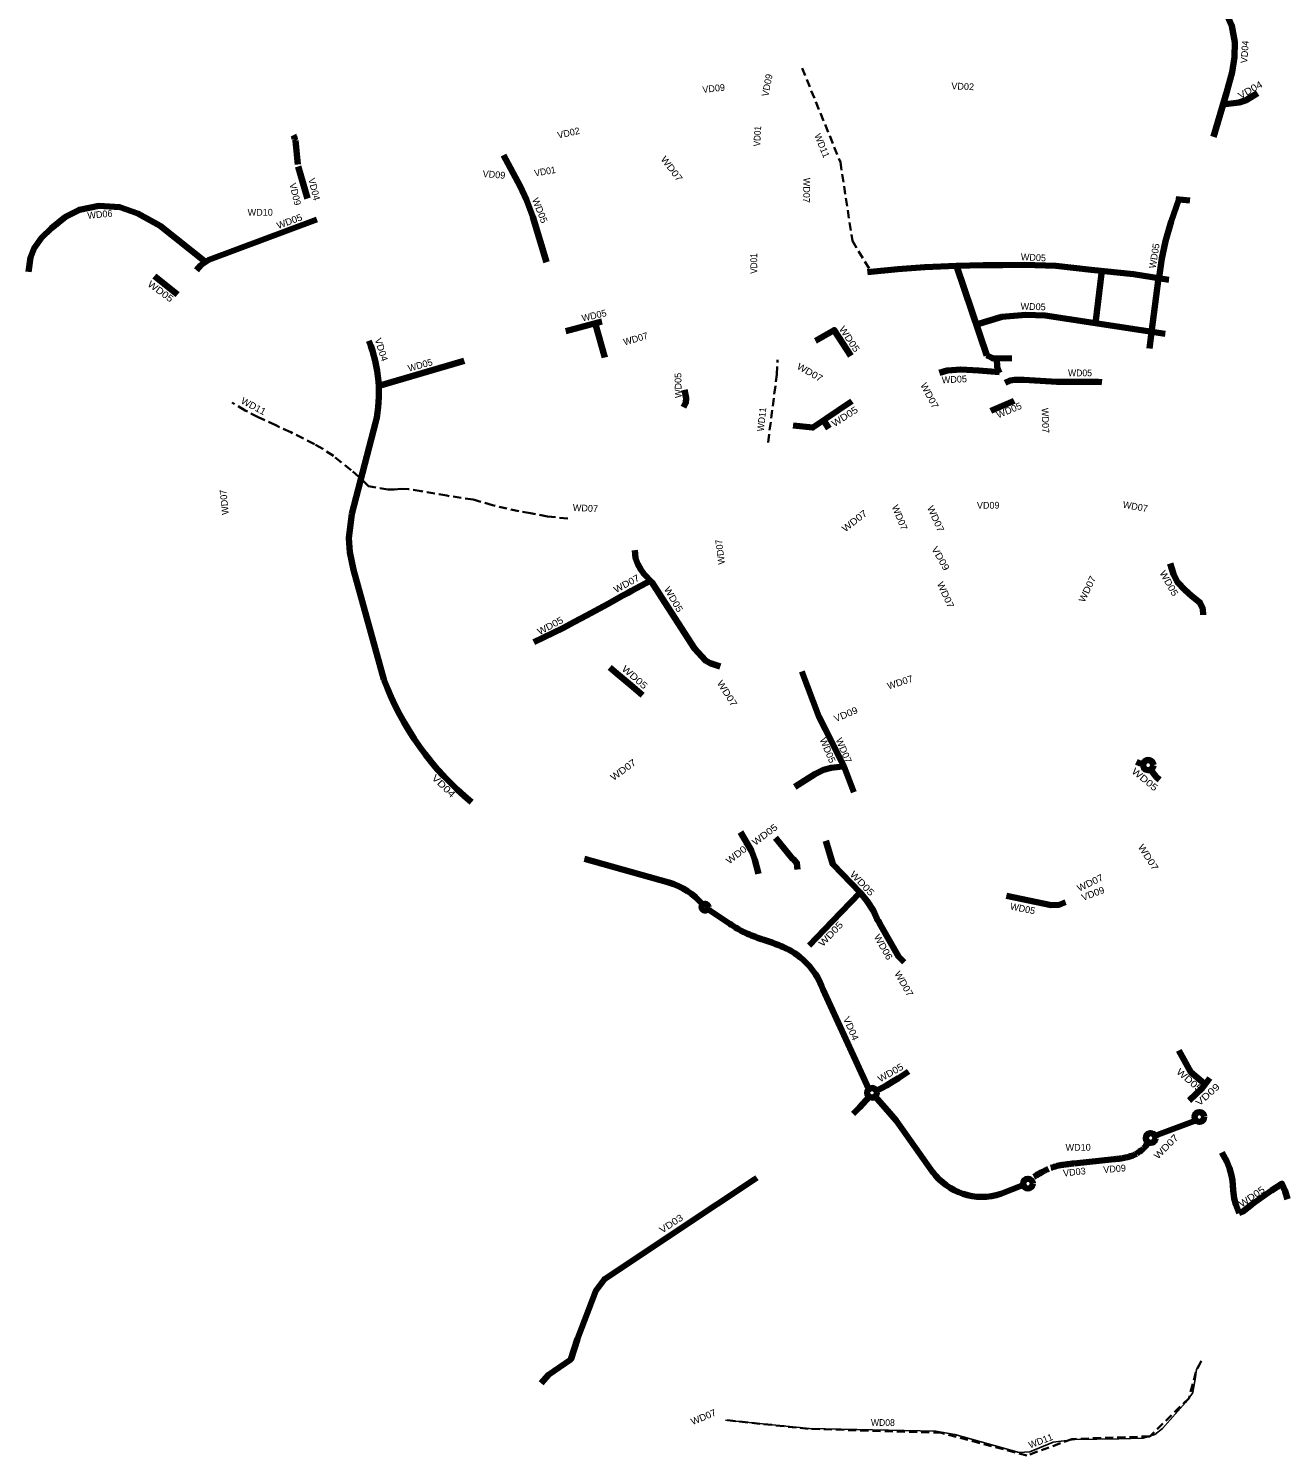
# Model space of a CAD drawing. Extents: x -650082 to -644047, y -1073134 to -1066669.
# Drawn here: x -650082 to -646363, y -1073058 to -1068842 of the extents above; entities that cross this region are included whole.
import ezdxf

# ---------------------------------------------------------------- set-up
doc = ezdxf.new("R2010")
doc.units = 0
doc.header["$LTSCALE"] = 8
doc.linetypes.add('MEDIUM_DASHED', pattern=[4.5, 3, -1.5])
for name, color, linetype in [('1', 7, 'Continuous'), ('10', 7, 'Continuous'), ('14', 7, 'Continuous'), ('2', 7, 'Continuous'), ('3', 7, 'Continuous'), ('4', 7, 'Continuous'), ('5', 7, 'Continuous'), ('6', 7, 'Continuous'), ('7', 7, 'Continuous'), ('9', 7, 'Continuous')]:
    doc.layers.add(name, color=color, linetype=linetype)
for name, color, linetype, lineweight in [('11', 7, 'Continuous', 106), ('12', 7, 'Continuous', 106), ('13', 7, 'MEDIUM_DASHED', 35), ('47', 7, 'Continuous', 106), ('51', 7, 'Continuous', 106), ('8', 7, 'Continuous', 25)]:
    doc.layers.add(name, color=color, linetype=linetype, lineweight=lineweight)

msp = doc.modelspace()

# ---------------------------------------------------------------- linework, layer by layer
at = {"layer": '11'}
for p, q in [((-649286.296, -1069243.402), (-649294.037, -1069172.192)), ((-649258.547, -1069344.39), (-649285.681, -1069249.06)), ((-649126.823, -1070275.677), (-649056.809, -1070006.786)), ((-648190.636, -1071365.392), (-648439.544, -1071295.299)), ((-647735.858, -1071680.067), (-647599.793, -1071975.634))]:
    msp.add_line(p, q, dxfattribs=at)
for points in [[(-646581.274, -1069162.086), (-646543.734, -1069031.454), (-646526.307, -1068970.81), (-646520.034, -1068926.895), (-646519.124, -1068882.525), (-646527.13, -1068833.717), (-646541.089, -1068803.463), (-646555.823, -1068777.863), (-646576.76, -1068753.039), (-646603.929, -1068734.295), (-646632.204, -1068718.474)], [(-646553.797, -1069066.473), (-646505.955, -1069060.333), (-646484.805, -1069053.474), (-646451.286, -1069033.122)], [(-649126.823, -1070275.677), (-649136.116, -1070347.82), (-649133.06, -1070389.586), (-649121.855, -1070441.538), (-649032.534, -1070765.134)], [(-648075.374, -1071443.872), (-648022.004, -1071479.581), (-648016.461, -1071483.285), (-648010.907, -1071486.974), (-648005.332, -1071490.629), (-647999.724, -1071494.234), (-647994.074, -1071497.773), (-647988.372, -1071501.227), (-647982.61, -1071504.58), (-647976.78, -1071507.812), (-647970.874, -1071510.906), (-647963.887, -1071513.957), (-647958.108, -1071516.621), (-647952.275, -1071519.164), (-647946.395, -1071521.599), (-647940.477, -1071523.938), (-647934.527, -1071526.195), (-647928.551, -1071528.382), (-647922.556, -1071530.515), (-647916.545, -1071532.605), (-647910.525, -1071534.668), (-647904.5, -1071536.717), (-647895.595, -1071539.745), (-647889.576, -1071541.81), (-647883.568, -1071543.908), (-647877.578, -1071546.054), (-647871.61, -1071548.265), (-647865.673, -1071550.555), (-647859.774, -1071552.942), (-647853.921, -1071555.438), (-647848.123, -1071558.061), (-647842.39, -1071560.823), (-647836.733, -1071563.738)]]:
    msp.add_lwpolyline(points, dxfattribs=at)
msp.add_circle((-648083.781, -1071438.172), 10.157, dxfattribs=at)
for centre, radius, start, end in [((-649390.897, -1069197.054), 100, 14.39558, 23.46117), ((-649452.625, -1069917.995), 405.652, 347.35635, 22.18649), ((-648232.695, -1070467.567), 853.398, 200.40686, 230.69896), ((-648244.965, -1071557.871), 200, 39.49461, 74.23772), ((-647937.958, -1071753.418), 215, 19.9479, 61.91292)]:
    msp.add_arc(centre, radius, start, end, dxfattribs=at)
at = {"layer": '12'}
for p, q in [((-646754.674, -1072114.023), (-646633.694, -1072068.165)), ((-646993.404, -1072195.535), (-646875.615, -1072182.532)), ((-647145.028, -1072259.442), (-647209.69, -1072285.315))]:
    msp.add_line(p, q, dxfattribs=at)
for points in [[(-647646.641, -1072049.031), (-647627.876, -1072030.328), (-647598.733, -1071998.754)], [(-647581.398, -1071997.866), (-647544.374, -1072039.387), (-647519.615, -1072068.332), (-647409.551, -1072222.875)], [(-646876.248, -1072183.165), (-646872.383, -1072182.737), (-646868.519, -1072182.3), (-646864.657, -1072181.844), (-646860.798, -1072181.36), (-646856.944, -1072180.839), (-646853.097, -1072180.272), (-646849.258, -1072179.649), (-646845.43, -1072178.963), (-646841.617, -1072178.202), (-646837.82, -1072177.36), (-646834.045, -1072176.427), (-646830.296, -1072175.394), (-646826.578, -1072174.254), (-646822.898, -1072172.998), (-646819.262, -1072171.619), (-646815.677, -1072170.111), (-646812.154, -1072168.466), (-646808.701, -1072166.678)], [(-647112.659, -1072235.417), (-647108.405, -1072232.79), (-647104.143, -1072230.176), (-647099.863, -1072227.591), (-647095.557, -1072225.05), (-647091.218, -1072222.565), (-647086.838, -1072220.154), (-647082.411, -1072217.83), (-647077.93, -1072215.611), (-647073.393, -1072213.512), (-647068.794, -1072211.549)], [(-647062.642, -1072208.565), (-647057.907, -1072206.959), (-647053.125, -1072205.5), (-647048.303, -1072204.179), (-647043.448, -1072202.984), (-647038.565, -1072201.905), (-647033.661, -1072200.931), (-647028.739, -1072200.051), (-647023.804, -1072199.253), (-647018.857, -1072198.525), (-647013.902, -1072197.856), (-647008.941, -1072197.235), (-647003.975, -1072196.649), (-646999.007, -1072196.086), (-646994.037, -1072195.536)], [(-647930.391, -1072238.053), (-647936.91, -1072242.12), (-648048.17, -1072316.094), (-648380.845, -1072537.281), (-648405.937, -1072571.667), (-648460.352, -1072713.39), (-648480.403, -1072774.677), (-648546.627, -1072820.111), (-648567.38, -1072844.77)]]:
    msp.add_lwpolyline(points, dxfattribs=at)
for centre in [(-647590.655, -1071986.8), (-646623.358, -1072058.099), (-646767.624, -1072120.384), (-647130.12, -1072255.012)]:
    msp.add_circle(centre, 14.428, dxfattribs=at)
for centre, radius, start, end in [((-646851.756, -1072087.012), 90, 298.5808, 324.78461), ((-647266.212, -1072116.452), 178.071, 215.23547, 288.50636)]:
    msp.add_arc(centre, radius, start, end, dxfattribs=at)
at = {"layer": '13'}
for points in [[(-647796.971, -1068958.769), (-647683.968, -1069236.597), (-647648.396, -1069468.745), (-647594.062, -1069560.317), (-647340.265, -1069541.717), (-647253.655, -1069810.08), (-647231.91, -1069823.971)], [(-647897.53, -1070064.61), (-647871.671, -1069864.156), (-647869.45, -1069820.63)], [(-648489.42, -1070289.79), (-648549.11, -1070283.64), (-648599.41, -1070274.03), (-648633.75, -1070268.38), (-648711.24, -1070250.44), (-648768.32, -1070233.86), (-648846.76, -1070222.17), (-648921.87, -1070208.67), (-648959.67, -1070203.09), (-648981.35, -1070202.4), (-649002.23, -1070203.94), (-649021.05, -1070203.56), (-649078.099, -1070194.501), (-649106.06, -1070166.8), (-649129.57, -1070146.73), (-649181.7, -1070104.45), (-649213.21, -1070083.53), (-649237.78, -1070069.79), (-649307.84, -1070034.18), (-649351.66, -1070014.26), (-649403.65, -1069989.85), (-649442.47, -1069970.36), (-649481, -1069947.32)], [(-646618.098, -1072779.957), (-646633.878, -1072812.319), (-646654.064, -1072888.773), (-646770.097, -1073001.842), (-647000.119, -1073009.906), (-647132.968, -1073058.363), (-647385.213, -1072991.734), (-647778.715, -1072979.619), (-648025.915, -1072953.371)]]:
    msp.add_lwpolyline(points, dxfattribs=at)
at = {"layer": '47'}
for p, q in [((-646692.985, -1069346.026), (-646651.217, -1069350.274)), ((-647339.967, -1069545.744), (-647251.088, -1069808.426)), ((-646912.03, -1069558.076), (-646930.389, -1069712.594)), ((-649642.332, -1069628.173), (-649710.271, -1069574.044)), ((-647207.164, -1069694.062), (-647282.295, -1069716.194)), ((-648494.915, -1069736.521), (-648388.804, -1069707.486)), ((-648379.302, -1069814.125), (-648408.537, -1069712.885)), ((-649043.757, -1069896.46), (-648795.401, -1069824.199)), ((-647170.402, -1069942.221), (-647239.362, -1069971.673)), ((-647718.115, -1070024.038), (-647733.777, -1069999.441)), ((-647672.743, -1071023.641), (-647643.873, -1071098.745)), ((-646808.839, -1071008.864), (-646795.926, -1071014.301)), ((-647824.318, -1071296.38), (-647875.239, -1071233.632)), ((-647708.122, -1071480.45), (-647626.882, -1071395.872)), ((-647708.122, -1071480.45), (-647775.697, -1071551.243))]:
    msp.add_line(p, q, dxfattribs=at)
for points in [[(-648552.408, -1069532.362), (-648592.697, -1069398.642), (-648611.424, -1069347.704), (-648629.402, -1069308.002), (-648679.548, -1069216.178)], [(-646742.322, -1069576.725), (-646734.087, -1069520.908), (-646723.107, -1069469.667), (-646706.636, -1069412.02), (-646684.285, -1069346.911)], [(-649586.177, -1069556.212), (-649573.053, -1069541.298), (-649550.047, -1069525.713), (-649230.786, -1069405.644)], [(-647603.51, -1069561.425), (-647514.414, -1069553.281), (-647434.342, -1069547.122), (-647341.331, -1069542.596), (-647262.07, -1069540.647), (-647204.248, -1069540.647), (-647140.134, -1069540.07), (-647047.049, -1069543.256), (-646943.2, -1069554.795), (-646817.923, -1069567.982), (-646714.075, -1069584.466)], [(-646744.044, -1069579.015), (-646764.641, -1069739.238), (-646770.927, -1069787.596)], [(-646724.352, -1069743.581), (-647078.839, -1069690.268), (-647135.789, -1069688.123), (-647207.164, -1069694.062)], [(-647757.476, -1069764.575), (-647701.982, -1069733.103), (-647653.087, -1069809.089)], [(-647251.088, -1069808.426), (-647232.613, -1069816.264), (-647177.241, -1069817.194)], [(-647213.795, -1069859.205), (-647220.933, -1069841.605), (-647221.408, -1069819.284)], [(-647390.821, -1069859.073), (-647368.021, -1069852.558), (-647328.004, -1069849.767), (-647274.492, -1069852.093), (-647213.899, -1069857.686)], [(-647197.567, -1069888.373), (-647182.853, -1069882.067), (-647168.927, -1069879.439), (-647141.6, -1069879.965), (-647044.065, -1069885.918), (-646922.882, -1069885.918), (-646911.17, -1069886.938)], [(-648147.091, -1069960.576), (-648140.266, -1069946.926), (-648139.508, -1069934.035), (-648144.058, -1069909.01)], [(-647650.097, -1069942.883), (-647765.549, -1070020.915), (-647823.598, -1070014.961)], [(-648290.966, -1070383.374), (-648288.845, -1070406.899), (-648282.079, -1070425.044), (-648273.16, -1070440.728), (-648264.17, -1070453.236), (-648241.202, -1070478.118), (-648211.195, -1070523.918)], [(-646709.343, -1070422.319), (-646700.372, -1070454.216), (-646687.863, -1070477.44), (-646666.258, -1070500.316), (-646645.289, -1070519.379), (-646621.777, -1070537.807), (-646613.517, -1070556.235), (-646612.246, -1070574.663)], [(-648589.664, -1070655.082), (-648504.268, -1070613.585), (-648469.046, -1070594.986), (-648434.122, -1070576.22), (-648370.201, -1070541.371), (-648326.641, -1070517.498), (-648313.175, -1070510.435), (-648300.652, -1070503.633), (-648244.358, -1070473.301)], [(-648039.532, -1070726.638), (-648068.169, -1070717.378), (-648082.709, -1070709.44), (-648115.092, -1070674.163), (-648211.195, -1070523.918)], [(-648268.369, -1070811.262), (-648303.087, -1070781.942), (-648344.753, -1070748.129), (-648364.772, -1070729.983)], [(-647798.303, -1070741.695), (-647747.4, -1070874.36), (-647727.829, -1070913.158), (-647672.743, -1071023.641)], [(-647677.55, -1071022.921), (-647710.774, -1071025.971), (-647733.735, -1071032.504), (-647759.543, -1071045.17), (-647818.707, -1071082.607)], [(-646741.751, -1071062.202), (-646751.573, -1071052.898), (-646766.082, -1071034.526)], [(-647925.368, -1071339.891), (-647936.852, -1071298.253), (-647946.561, -1071272.093), (-647978.731, -1071216.254)], [(-647727.338, -1071242.207), (-647706.62, -1071310.667), (-647625.213, -1071395.211), (-647604.958, -1071420.095), (-647586.504, -1071448.747), (-647573.087, -1071478.317)], [(-647810.393, -1071327.127), (-647812.572, -1071307.894), (-647823.337, -1071295.659)], [(-647193.49, -1071404.445), (-647061.509, -1071431.827), (-647037.352, -1071430.861), (-647019.146, -1071423.327)], [(-646684.409, -1071862), (-646648.676, -1071926.01), (-646609.296, -1071959.529)], [(-647577.687, -1071980.477), (-647548.027, -1071965.02), (-647528.6, -1071953.175), (-647512.49, -1071943.224), (-647482.989, -1071923.852)], [(-646592.707, -1071943.76), (-646614.335, -1071972.381), (-646653.429, -1072008.981)], [(-646556.924, -1072163.008), (-646541.975, -1072190.142), (-646534.08, -1072209.348), (-646528.451, -1072231.169), (-646526.022, -1072245.895), (-646524.078, -1072274.419), (-646520.515, -1072298.567), (-646515.575, -1072317.043), (-646505.446, -1072341.949)], [(-646505.446, -1072341.949), (-646496.463, -1072338.193), (-646468.402, -1072317.124), (-646451.071, -1072304.158), (-646409.932, -1072275.634), (-646379.686, -1072255.456), (-646370.251, -1072277.255), (-646363.282, -1072301.269)]]:
    msp.add_lwpolyline(points, dxfattribs=at)
msp.add_circle((-646774.452, -1071018.284), 15.055, dxfattribs=at)
at = {"layer": '51'}
for points in [[(-649558.921, -1069531.725), (-649693.075, -1069424.839), (-649759.229, -1069388.516), (-649812.457, -1069370.063), (-649874.912, -1069365.805), (-649931.689, -1069377.161), (-649972.852, -1069398.452), (-650014.541, -1069431.96), (-650043.673, -1069460), (-650065.774, -1069491.142), (-650076.339, -1069518.627), (-650082.165, -1069560.934)], [(-647572.568, -1071477.763), (-647563.965, -1071494.251), (-647512.351, -1071583.86), (-647495.989, -1071600.795)]]:
    msp.add_lwpolyline(points, dxfattribs=at)
at = {"layer": '8'}
for points in [[(-646641.615, -1072861.847), (-646642.788, -1072871.592), (-646636.323, -1072833.305), (-646631.944, -1072804.277), (-646618.055, -1072778.52)], [(-648023.648, -1072953.961), (-647775.451, -1072978.577), (-647402.33, -1072986.644), (-647345.858, -1072996.728), (-647156.272, -1073049.167), (-647124.002, -1073047.15), (-647055.429, -1073018.914), (-646990.889, -1073010.846), (-646861.81, -1073008.83), (-646789.202, -1073006.813), (-646754.915, -1072996.728), (-646732.73, -1072978.577), (-646664.156, -1072901.935), (-646642.762, -1072873.366)]]:
    msp.add_lwpolyline(points, dxfattribs=at)

# ---------------------------------------------------------------- texts
at = {"layer": '1'}
for rotation, width, p in [(86.772, 0.9, (-647921.103, -1069190.627)), (9.97, 0.95, (-648586.178, -1069279.341)), (90.083, 0.9, (-647929.691, -1069566.304))]:
    msp.add_text('VD01', height=20, rotation=rotation, dxfattribs=dict(at, width=width)).set_placement(p)
at = {"layer": '10'}
for p in [(-649434.865, -1069395.02), (-647018.705, -1072158.017)]:
    msp.add_text('WD10', height=20, rotation=0.318, dxfattribs=at).set_placement(p)
at = {"layer": '14'}
for rotation, p in [(292.311, (-647761.508, -1069157.121)), (20.83, (-647123.491, -1073037.925))]:
    msp.add_text('WD11', height=20, rotation=rotation, dxfattribs=at).set_placement(p)
for rotation, width, p in [(332.078, 1.05, (-649456.64, -1069948.265)), (83.81, 0.95, (-647910.311, -1070032.951))]:
    msp.add_text('WD11', height=20, rotation=rotation, dxfattribs=dict(at, width=width)).set_placement(p)
at = {"layer": '2'}
for rotation, p in [(357.375, (-647356.457, -1069021.082)), (12.542, (-648517.473, -1069167.221))]:
    msp.add_text('VD02', height=20, rotation=rotation, dxfattribs=at).set_placement(p)
at = {"layer": '3'}
msp.add_text('VD03', height=20, rotation=6.009, dxfattribs=at).set_placement((-647025.037, -1072234.169))
at = {"layer": '3', "width": 1.15}
msp.add_text('VD03', height=20, rotation=33.391, dxfattribs=at).set_placement((-648210.42, -1072403.064))
at = {"layer": '4'}
for rotation, p in [(85.893, (-646482.108, -1068944.939)), (284.235, (-649256.065, -1069286.662))]:
    msp.add_text('VD04', height=20, rotation=rotation, dxfattribs=at).set_placement(p)
for rotation, width, p in [(29.411, 1.15, (-646502.014, -1069050.708)), (287.6, 1.05, (-649060.021, -1069760.208)), (316.159, 1.25, (-648893.138, -1071058.344)), (293.494, 1.1, (-647676.428, -1071767.021))]:
    msp.add_text('VD04', height=20, rotation=rotation, dxfattribs=dict(at, width=width)).set_placement(p)
at = {"layer": '5'}
for rotation, width, p in [(291.57, 1.05, (-648595.322, -1069346.682)), (20.413, 1.05, (-649344.656, -1069434.505)), (323.794, 1.15, (-649732.394, -1069601.306)), (303.586, 1.15, (-647689.055, -1069729.375)), (359.771, 0.95, (-647011.407, -1069869.205)), (22.562, 1.05, (-647217.993, -1069994.051)), (32.763, 1.15, (-647701.559, -1070019.86)), (299.409, 1.1, (-646742.052, -1070450.235)), (300.371, 1.1, (-648205.967, -1070498.405)), (27.93, 1.1, (-648572.628, -1070634.584)), (318.812, 1.2, (-648331.556, -1070736.821)), (292.87, 1.05, (-647745.74, -1070942.497)), (320.604, 1.2, (-646825.309, -1071040.045)), (36.91, 1.15, (-647935.396, -1071257.441)), (313.863, 1.2, (-647657.525, -1071342.864)), (46.414, 1.2, (-647735.69, -1071556.53)), (29.944, 1.1, (-647566.364, -1071956.55)), (319.129, 1.2, (-646693.266, -1071927.68)), (34.487, 1.15, (-646498.118, -1072326.083))]:
    msp.add_text('WD05', height=20, rotation=rotation, dxfattribs=dict(at, width=width)).set_placement(p)
for rotation, p in [(80.615, (-646752.852, -1069551.846)), (357.197, (-647151.356, -1069526.302)), (358.177, (-647151.994, -1069672.198)), (12.814, (-648445.492, -1069707.786)), (15.559, (-648958.337, -1069856.049)), (90.808, (-648152.699, -1069933.435)), (2.857, (-647383.984, -1069890.409)), (348.607, (-647183.65, -1071444.769))]:
    msp.add_text('WD05', height=20, rotation=rotation, dxfattribs=at).set_placement(p)
at = {"layer": '6'}
msp.add_text('WD06', height=20, rotation=5.442, dxfattribs=at).set_placement((-649907.373, -1069404.507))
at = {"layer": '6', "width": 1.1}
msp.add_text('WD06', height=20, rotation=299.586, dxfattribs=at).set_placement((-647586.001, -1071525.44))
at = {"layer": '7'}
for rotation, width, p in [(307.201, 1.15, (-648216.084, -1069228.211)), (330.302, 1.1, (-647814.4, -1069846.044)), (297.667, 1.1, (-647448.246, -1069895.109)), (37.889, 1.15, (-647669.893, -1070330.992)), (292.116, 1.05, (-647532.629, -1070254.406)), (294.454, 1.1, (-647428.465, -1070257.434)), (28.414, 1.1, (-648346.892, -1070510.452)), (294.454, 1.1, (-647399.207, -1070482.213)), (64.535, 1.1, (-646963.014, -1070539.33)), (302.302, 1.15, (-648049.847, -1070775.71)), (17.803, 1.05, (-647541.835, -1070795.135)), (293.26, 1.05, (-647698.608, -1070943.099)), (36.212, 1.15, (-648354.157, -1071065.604)), (37.876, 1.15, (-648012.3, -1071312.413)), (302.643, 1.15, (-646805.959, -1071260.156)), (25.46, 1.1, (-646978.911, -1071392.769)), (299.885, 1.1, (-647525.38, -1071634.155)), (45.026, 1.2, (-646746.182, -1072184.521)), (22.432, 1.05, (-648120.604, -1072968.926))]:
    msp.add_text('WD07', height=20, rotation=rotation, dxfattribs=dict(at, width=width)).set_placement(p)
for rotation, p in [(269.034, (-647793.034, -1069282.646)), (16.02, (-648321.58, -1069778.479)), (272.013, (-647089.498, -1069963.268)), (95.41, (-649490.694, -1070277.596)), (349.845, (-646850.986, -1070257.62)), (357.034, (-648474.765, -1070267.044)), (97.026, (-648024.784, -1070424.219))]:
    msp.add_text('WD07', height=20, rotation=rotation, dxfattribs=at).set_placement(p)
at = {"layer": '8', "width": 0.95}
msp.add_text('WD08', height=20, rotation=359.822, dxfattribs=at).set_placement((-647593.734, -1072970.888))
at = {"layer": '9'}
for rotation, p in [(78.961, (-647896.883, -1069044.007)), (6.253, (-648090.523, -1069032.33)), (355.112, (-648741.445, -1069280.24)), (283.42, (-649311.686, -1069300.906)), (0.216, (-647280.667, -1070260.641)), (4.69, (-646906.544, -1072223.962))]:
    msp.add_text('VD09', height=20, rotation=rotation, dxfattribs=at).set_placement(p)
for rotation, width, p in [(299.658, 1.15, (-647415.603, -1070379.066)), (22.494, 1.1, (-647698.244, -1070891.729)), (20.79, 1.05, (-646967.13, -1071419.926)), (41.768, 1.25, (-646623.484, -1072027.315))]:
    msp.add_text('VD09', height=20, rotation=rotation, dxfattribs=dict(at, width=width)).set_placement(p)

doc.saveas('drawing.dxf')
